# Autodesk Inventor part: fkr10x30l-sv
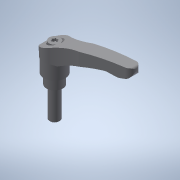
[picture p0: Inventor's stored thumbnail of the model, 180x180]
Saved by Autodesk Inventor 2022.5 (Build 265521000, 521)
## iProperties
Created: 2017-09
Part Number: fkr10x30l-sv
Material: 一般
Document SubType Name: Modeling
Designer: imaocorp
Density: 1 g/cm^3
Appearance: 既定
Author: imaocorp
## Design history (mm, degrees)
node "fkr10x30l-sv.x_t1"
node "fkr10x30l-sv"
node "Base1"
